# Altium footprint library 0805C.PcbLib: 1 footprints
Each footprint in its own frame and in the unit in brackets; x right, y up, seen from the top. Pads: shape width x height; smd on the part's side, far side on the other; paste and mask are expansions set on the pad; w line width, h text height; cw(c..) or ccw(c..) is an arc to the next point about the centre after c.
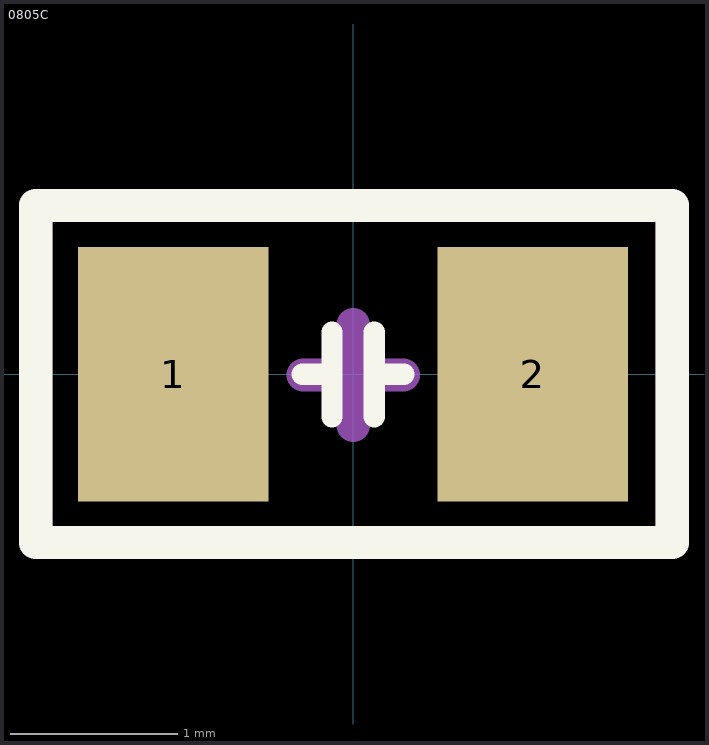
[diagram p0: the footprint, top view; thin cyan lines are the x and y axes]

## 0805C [mil]
pads (2):
  rect 45x60 smd: 1(-42.4,0) 2(42.4,0)
Top Overlay:
  lines w5: -12,0 -5,0 ; -5,-10 -5,10 ; 5,-10 5,10 ; 5,0 12,0
  lines w7.87: -74.83,-39.69 -74.83,39.81 75.26,39.81 75.26,-39.69 -74.83,-39.69
Mechanical 15:
  lines w7.87: -11.78,-0.18 11.84,-0.18 ; 0.03,-11.99 0.03,11.63 ; -74.83,-39.69 -74.83,39.81 75.26,39.81 75.26,-39.69 -74.83,-39.69
3D body "Cap 0805.step": height 30.79, standoff 0, extent -39.77,-23.6 38.97,25.61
